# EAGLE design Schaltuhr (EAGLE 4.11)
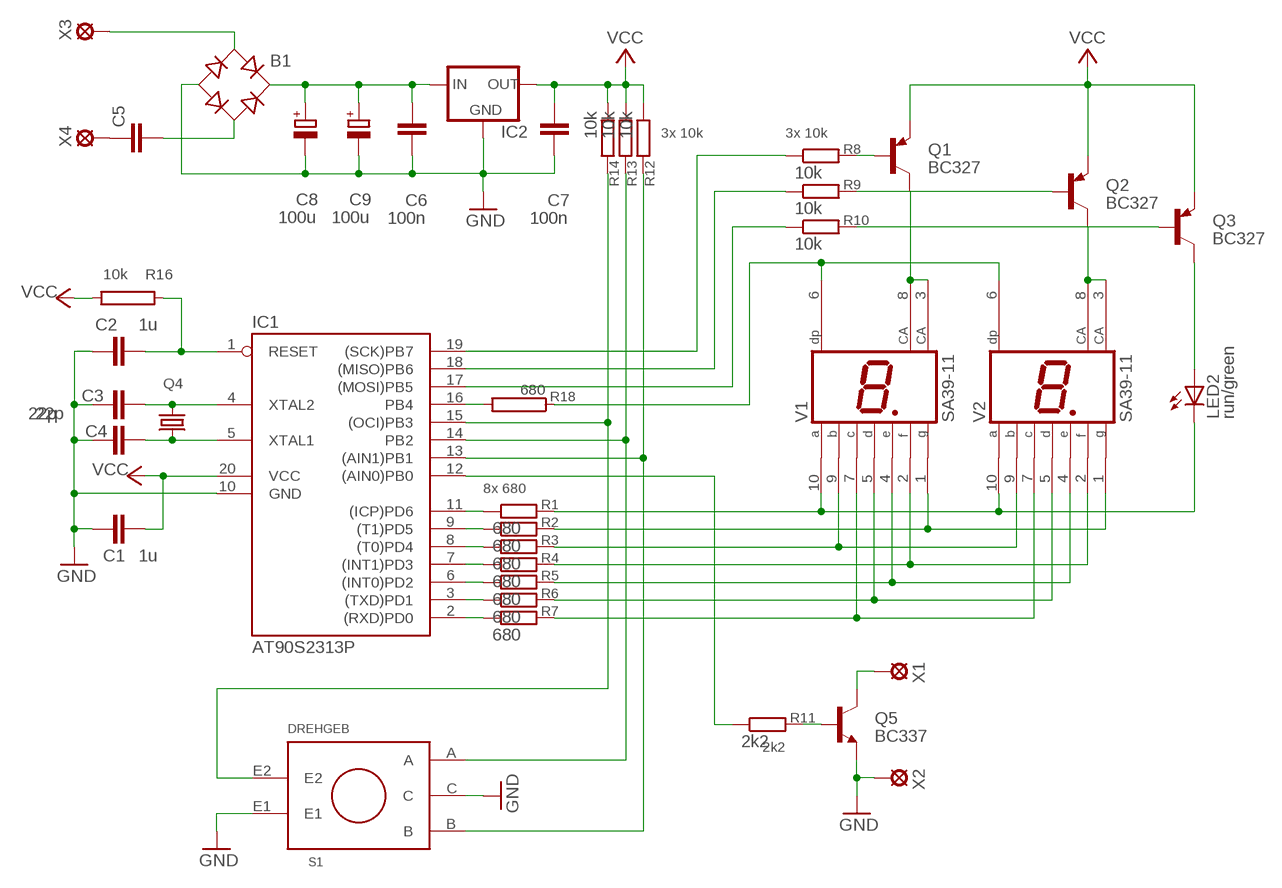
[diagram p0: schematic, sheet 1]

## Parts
B1  B-DIL  [B-DIL]
C1  1u  C-EU050-025X075  [C050-025X075]
C2  1u  C-EU050-025X075  [C050-025X075]
C3  22p  C-EU025-024X044  [C025-024X044]
C4  22p  C-EU025-024X044  [C025-024X044]
C5  C-EU102-043X133  [C102-043X133]
C6  100n  C-EU050-024X044  [C050-024X044]
C7  100n  C-EU050-024X044  [C050-024X044]
C8  100u  CPOL-EUE2.5-7  [E2,5-7]
C9  100u  CPOL-EUE2.5-7  [E2,5-7]
IC1  AT90S2313P  [DIL20]
IC2  78LXX  [78LXX]
LED2  run/green  LED3MM  [LED3MM]
Q1  BC327  [TO92]
Q2  BC327  [TO92]
Q3  BC327  [TO92]
Q4  HC49U-V  [HC49U-V]
Q5  BC337  [TO92]
R1  680  R-EU_R0805  [R0805]
R2  680  R-EU_R0805  [R0805]
R3  680  R-EU_R0805  [R0805]
R4  680  R-EU_R0805  [R0805]
R5  680  R-EU_R0805  [R0805]
R6  680  R-EU_R0805  [R0805]
R7  680  R-EU_R0805  [R0805]
R8  10k  R-EU_0207/10  [0207/10]
R9  10k  R-EU_0207/10  [0207/10]
R10  10k  R-EU_0207/10  [0207/10]
R11  2k2  R-EU_0207/10  [0207/10]
R12  10k  R-EU_0207/10  [0207/10]
R13  10k  R-EU_0207/10  [0207/10]
R14  10k  R-EU_0207/10  [0207/10]
R16  10k  0207/10@2  [1206]
R18  680  0207/10@2  [1206]
S1  DREHGEB  [DREHGEB]
V1  SA39-11  [HDSP-E]
V2  SA39-11  [HDSP-E]
X1  MCS10B  [MCS10B]
X2  MCS10B  [MCS10B]
X3  MCS10B  [MCS10B]
X4  MCS10B  [MCS10B]

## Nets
/RESET: C2.2 IC1.1(RESET) R16.1
A: LED2.K(C) R1.2 V1.10(A) V2.10(A)
B: R3.2 V1.9(B) V2.9(B)
C: R7.2 V1.7(C) V2.7(C)
D: R6.2 V1.5(D) V2.5(D)
E: R5.2 V1.4(E) V2.4(E)
F: R4.2 V1.2(F) V2.2(F)
G: R2.2 V1.1(G) V2.1(G)
GND: B1.- C1.1 C2.1 C3.1 C4.1 C6.1 C7.1 C8.- C9.- IC1.10(GND) IC2.GND Q5.1(E) S1.C S1.E1 X2.MP
N$1: IC1.17((MOSI)PB5) R10.1
N$2: Q2.3(C) V2.3(CA) V2.8(CA)
N$3: Q1.3(C) V1.3(CA) V1.8(CA)
N$4: Q2.2(B) R9.2
N$5: Q3.2(B) R10.2
N$6: Q1.2(B) R8.2
N$7: IC1.11((ICP)PD6) R1.1
N$8: IC1.9((T1)PD5) R2.1
N$9: IC1.8((T0)PD4) R3.1
N$10: IC1.7((INT1)PD3) R4.1
N$11: IC1.6((INT0)PD2) R5.1
N$12: IC1.3((TXD)PD1) R6.1
N$13: IC1.2((RXD)PD0) R7.1
N$14: IC1.12((AIN0)PB0) R11.1
N$15: C3.2 IC1.4(XTAL2) Q4.1
N$16: C4.2 IC1.5(XTAL1) Q4.2
N$17: Q5.3(C) X1.MP
N$18: LED2.A Q3.3(C)
N$19: IC1.18((MISO)PB6) R9.1
N$20: IC1.19((SCK)PB7) R8.1
N$21: B1.AC2 C5.2
N$22: Q5.2(B) R11.2
N$23: IC1.15((OCI)PB3) R14.2 S1.E2
N$24: IC1.14(PB2) R13.2 S1.A
N$25: IC1.13((AIN1)PB1) R12.2 S1.B
N$27: B1.+ C6.2 C8.+ C9.+ IC2.IN
N$28: B1.AC1 X3.MP
N$29: C5.1 X4.MP
N$31: IC1.16(PB4) R18.2
N$32: R18.1 V1.6(DP) V2.6(DP)
VCC: C1.2 C7.2 IC1.20(VCC) IC2.OUT Q1.1(E) Q2.1(E) Q3.1(E) R12.1 R13.1 R14.1 R16.2

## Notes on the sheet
- 3x 10k | 3x 10k
- 8x 680
- 2k2

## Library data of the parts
B1 = rectifier:B-DIL: RECTIFIER
C1-C7 = rcl:C-EU: CAPACITOR, European symbol
C8 C9 = rcl:CPOL-EU: POLARIZED CAPACITOR, European symbol
IC1 = atmel:AT90S2313: MICROCONTROLLER 2 Kbytes FLASH 128 bytes SRAM 128 bytes EEPROM UART
IC2 = v-reg:78LXX: VOLTAGE REGULATOR
LED2 = led:LED: LED
Q1-Q3 = transistor-pnp:BC327: PNP Transistor
Q4 = QUARTZ:HC49U-V
Q5 = transistor-npn:BC337*: NPN Transistor
R1-R14 = rcl:R-EU_: RESISTOR, European symbol
R16 R18 = R:0207/10@2
S1 = SWITCH:DREHGEB
V1 V2 = display-hp:SA39-11
X1-X4 = solpad:MCS10B: SOLDER PAD

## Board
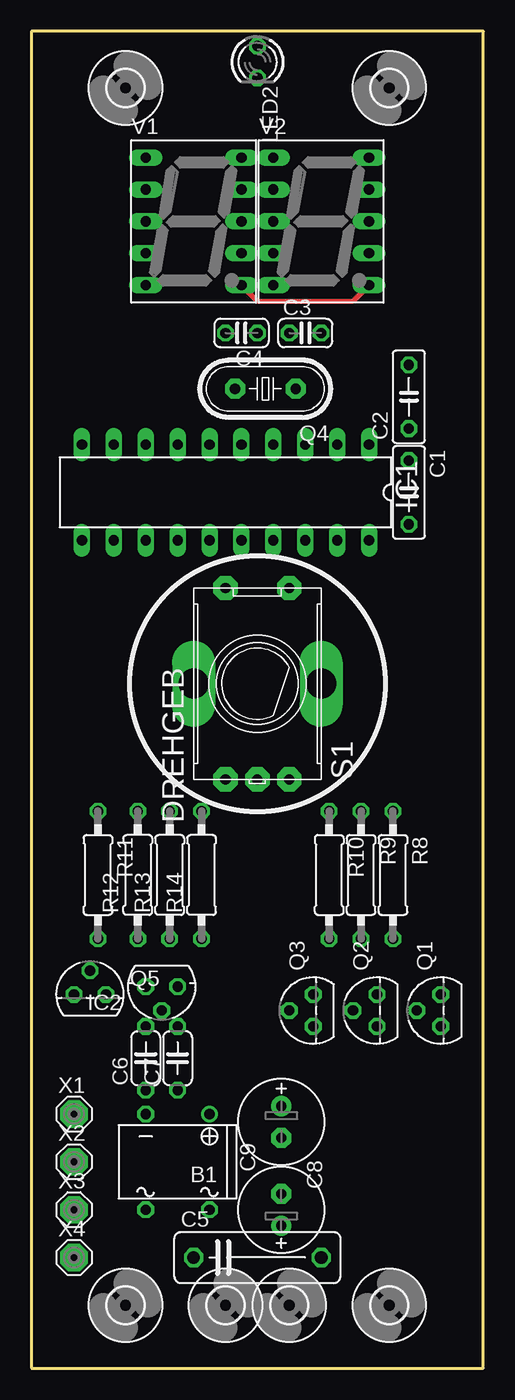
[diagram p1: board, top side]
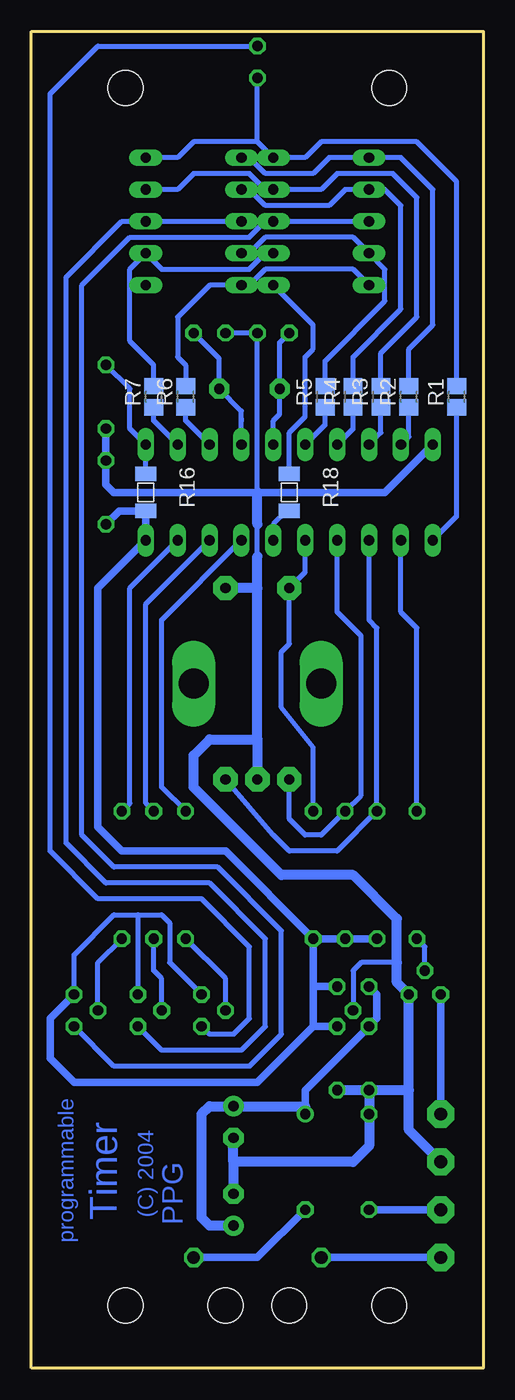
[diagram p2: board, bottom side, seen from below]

Size 36 x 106.5 mm. Coordinates in mm from the lower left corner, seen from the top.
Outline: 36,0 36,106.5 0,106.5 0,0 36,0
Copper layers (1*16): Top 0.035mm / dielectric 1.5mm / Bottom 0.035mm
Design rules "default": minimum track width 10mil, minimum drill 24mil, track to track 8mil, track to pad 8mil, pad to pad 8mil, via to via 8mil, smd to smd 8mil, copper to edge 40mil, drill to drill 8mil, minimum pad ring 10mil, minimum via ring 8mil, stop-mask expansion 4mil, vias tented up to drill 0mil, thermal gap 10mil

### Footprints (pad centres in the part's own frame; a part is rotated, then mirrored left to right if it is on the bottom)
B-DIL = drill 0.813 round: + -2.54,-3.81 | drill 0.813 octagon: - 2.54,-3.81; AC1 2.54,3.81; AC2 -2.54,3.81
C050-025X075 = drill 0.813 octagon: 1 -2.54,0; 2 2.54,0
C025-024X044 = drill 0.813 octagon: 1 -1.27,0; 2 1.27,0
C102-043X133 = drill 1.016 octagon: 1 -5.08,0; 2 5.08,0
C050-024X044 = drill 0.813 octagon: 1 -2.54,0; 2 2.54,0
E2,5-7 = drill 0.813 pad 1.6 round: + -1.27,0 | drill 0.813 pad 1.6 octagon: - 1.27,0
DIL20 = drill 0.813 long: 1 -11.43,-3.81; 2 -8.89,-3.81; 3 -6.35,-3.81; 4 -3.81,-3.81; 5 -1.27,-3.81; 6 1.27,-3.81; 7 3.81,-3.81; 8 6.35,-3.81; 9 8.89,-3.81; 10 11.43,-3.81; 11 11.43,3.81; 12 8.89,3.81; 13 6.35,3.81; 14 3.81,3.81; 15 1.27,3.81; 16 -1.27,3.81; 17 -3.81,3.81; 18 -6.35,3.81; 19 -8.89,3.81; 20 -11.43,3.81
78LXX = drill 0.813 octagon: GND 0,1.905; IN 1.27,0; OUT -1.27,0
LED3MM = drill 0.813 octagon: A -1.27,0; K 1.27,0
TO92 = drill 0.813 octagon: 1 1.27,0; 2 0,1.905; 3 -1.27,0
HC49U-V = drill 0.813 pad 1.6 octagon: 1 -2.413,0; 2 2.413,0
R0805 = smd 1.3 x 1.5: 1 -0.85,0; 2 0.85,0
0207/10 = drill 0.813 octagon: 1 -5.08,0; 2 5.08,0
1206 = smd 1.143 x 1.702: 1 -1.473,0; 2 1.473,0
DREHGEB = drill 0.8 pad 1.93 octagon: A 7.62,-2.54; B 7.62,2.54; C 7.62,0; E1 -7.62,2.54; E2 -7.62,-2.54 | drill 2.4 pad 3 long: M1 0,5.08; M2 0,-5.08
2,8 = hole 2.8: 0,0
HDSP-E = drill 0.813 long: 1 -3.81,5.08; 2 -3.81,2.54; 3 -3.81,0; 4 -3.81,-2.54; 5 -3.81,-5.08; 6 3.81,-5.08; 7 3.81,-2.54; 8 3.81,0; 9 3.81,2.54; 10 3.81,5.08
MCS10B = drill 1.016 pad 2.159 octagon: MP 0,0

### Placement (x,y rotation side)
B1  11.65,16.43 180 top
C1  30.06,69.77 270 top
C2  30.06,77.39 90 top
C3  21.81,82.47 0 top
C4  16.73,82.47 180 top
C5  18,8.81 0 top
C6  9.11,24.68 90 top
C7  11.65,24.68 90 top
C8  19.91,19.61 270 top
C9  19.91,12.62 90 top
IC1  15.46,69.77 180 top
IC2  10.38,30.4 180 top
LED2  18,104.06 270 top
Q1  32.61,28.5 90 top
Q2  27.52,28.5 90 top
Q3  22.45,28.5 90 top
Q4  18.64,78.03 180 top
Q5  4.66,29.77 0 top
R1  2.12,77.39 90 bottom
R2  5.94,77.39 90 bottom
R3  8.16,77.39 90 bottom
R4  10.38,77.39 90 bottom
R5  12.6,77.39 90 bottom
R6  23.71,77.39 90 bottom
R7  26.26,77.39 90 bottom
R8  28.8,39.29 270 top
R9  26.26,39.29 270 top
R10  23.71,39.29 270 top
R11  5.3,39.29 270 top
R12  8.47,39.29 90 top
R13  11.02,39.29 90 top
R14  13.55,39.29 90 top
R16  26.89,69.77 270 bottom
R18  15.46,69.77 270 bottom
S1  18,54.53 270 top
U$1  [2,8]  7.5,5 0 top
U$2  [2,8]  28.5,102 0 top
U$3  [2,8]  7.5,102 0 top
U$4  [2,8]  28.5,5 0 top
U$5  [2,8]  15.46,5 0 top
U$6  [2,8]  20.54,5 0 top
V1  12.92,91.36 0 top
V2  23.08,91.36 0 top
X1  3.39,20.24 0 top
X2  3.39,16.43 0 top
X3  3.39,12.62 0 top
X4  3.39,8.81 0 top

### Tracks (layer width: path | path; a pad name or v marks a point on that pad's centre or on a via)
/RESET  (via drill 0.61)
  Bottom 0.406: C2.2 28.16,78.03 28.16,74.85 IC1.1 R16.1
  other vias: 30.06,79.93 26.89,73.58
A  (via drill 0.61)
  Bottom 0.406: 18,97.71 23.08,97.71 24.35,96.44 V2.10 | R1.2 2.12,94.53 5.3,97.71 12.92,97.71 14.19,96.44 V1.10 18,97.71 | 18,97.71 LED2.K
  other vias: 18,102.79 26.89,96.44 16.73,96.44
B  (via drill 0.61)
  Bottom 0.406: V2.9 24.35,93.9 23.08,95.17 18.64,95.17 17.36,93.9 V1.9 12.92,93.9 11.65,95.17 7.21,95.17 5.3,93.27 5.3,83.74 8.16,80.88 R3.2
  other vias: 26.89,93.9 16.73,93.9
C  (via drill 0.61)
  Bottom 0.406: V1.7 17.36,88.82 18.64,87.55 25.62,87.55 V2.7 28.16,87.55 28.16,81.83 26.26,79.93 R7.2
  other vias: 26.89,88.82 16.73,88.82
D  (via drill 0.61)
  Bottom 0.406: V1.5 10.38,87.55 17.36,87.55 18.64,86.28 V2.5 21.81,86.28 24.35,83.74 24.35,80.56 23.71,79.93 R6.2
  other vias: 19.27,86.28 9.11,86.28
E  (via drill 0.61)
  Bottom 0.406: R5.2 12.6,80.25 7.84,85.01 7.84,87.55 V1.4 10.38,90.09 17.36,90.09 18.64,88.82 V2.4
  other vias: 19.27,88.82 9.11,88.82
F  (via drill 0.61)
  Bottom 0.406: V2.2 18.64,93.9 17.36,92.63 12.29,92.63 11.02,93.9 V1.2 7.84,93.9 6.57,92.63 6.57,84.38 10.38,80.56 R4.2
  other vias: 19.27,93.9 9.11,93.9
G  (via drill 0.61)
  Bottom 0.406: V2.1 18.64,96.44 17.36,95.17 13.55,95.17 12.29,96.44 V1.1 6.57,96.44 4.03,93.9 4.03,83.11 5.94,81.2 R2.2
  other vias: 19.27,96.44 9.11,96.44
GND  (via drill 0.61)
  Bottom 0.406: C3.1 C4.1 18,69.77 | 18,64.69 18,67.23 | 6.89,32.3 9.74,32.3 10.38,31.67 v10.38,28.5
  Bottom 0.61: IC1.10 7.84,69.77 18,69.77 29.43,69.77 30.06,70.41 C1.1 C2.1
  Bottom 0.813: 18,62.15 18,64.69 | 18,67.23 18,69.77 | 18,50.09 S1.C | 18,50.09 21.81,50.09 23.08,48.81 23.08,46.27 16.09,39.29 10.38,39.29 6.89,35.8 6.89,32.3 6.89,30.72 v5.94,29.77 5.94,22.14 | 18,62.15 S1.E1 | 18,50.09 18,62.15 | X2.MP 5.94,18.97 5.94,22.14 | C6.1 C7.1 | C6.1 B1.- 9.11,17.7 10.38,16.43 19.91,16.43 | 19.91,16.43 C9.- | 19.91,16.43 C8.- | 5.94,22.14 C6.1
  other vias: 18,82.47 20.54,82.47 30.06,74.85 30.06,72.31 4.03,73.58 11.65,22.14 9.11,22.14 9.11,20.24 19.91,18.34 19.91,13.89
N$1  (via drill 0.61)
  Bottom 0.406: IC1.17 25.62,59.61 25.62,46.27 R10.1
  other vias: 19.27,65.96 23.71,44.37
N$2  (via drill 0.61)
  Bottom 0.406: V2.3 V2.8 28.8,91.36 33.24,86.92 33.24,41.83 30.06,38.66 21.81,38.66 17.36,34.21 17.36,27.23 19.27,25.32 25.62,25.32 Q2.3
  other vias: 26.89,91.36 19.27,91.36 27.52,27.23
N$3  (via drill 0.61)
  Bottom 0.406: V1.3 V1.8 17.36,91.36 18.64,90.09 28.16,90.09 31.97,86.28 31.97,42.47 29.43,39.92 21.18,39.92 16.09,34.84 16.09,26.59 18.64,24.05 29.43,24.05 Q1.3
  other vias: 16.73,91.36 9.11,91.36 32.61,27.23
N$4  (via drill 0.61)
  Bottom 0.406: Q2.2 25.62,31.04 26.26,31.67 R9.2
  other vias: 26.26,34.21 25.62,28.5
N$5  (via drill 0.61)
  Bottom 0.406: Q3.2 20.54,31.04 R10.2
  other vias: 23.71,34.21 20.54,28.5
N$6  (via drill 0.61)
  Bottom 0.406: Q1.2 30.7,32.3 R8.2
  other vias: 28.8,34.21 30.7,28.5
N$7  (via drill 0.61)
  Bottom 0.406: R1.1 2.12,67.87 IC1.11
  other vias: 4.03,65.96
N$8  (via drill 0.61)
  Bottom 0.406: IC1.9 5.94,74.22 R2.1
  other vias: 6.57,73.58
N$9  (via drill 0.61)
  Bottom 0.406: R3.1 8.16,74.53 IC1.8
  other vias: 9.11,73.58
N$10  (via drill 0.61)
  Bottom 0.406: R4.1 10.38,74.85 IC1.7
  other vias: 11.65,73.58
N$11  (via drill 0.61)
  Bottom 0.406: R5.1 12.6,75.17 IC1.6
  other vias: 14.19,73.58
N$12  (via drill 0.61)
  Bottom 0.406: R6.1 23.71,75.48 IC1.3
  other vias: 21.81,73.58
N$13  (via drill 0.61)
  Bottom 0.406: R7.1 26.26,75.48 IC1.2
  other vias: 24.35,73.58
N$14  (via drill 0.61)
  Bottom 0.406: R11.1 5.3,58.98 6.57,60.24 IC1.12
  other vias: 6.57,65.96 5.3,44.37
N$15  (via drill 0.61)
  Bottom 0.406: IC1.4 19.27,75.48 | 19.27,75.48 19.27,75.61 | C3.2 21.05,80.44 Q4.1 19.27,76.25 19.27,75.48
  other vias: 23.08,82.47 19.27,73.58
N$16  (via drill 0.61)
  Bottom 0.406: C4.2 16.22,81.71 Q4.2 16.22,75.99 16.73,75.48 IC1.5
  other vias: 15.46,82.47 16.73,73.58
N$17  (via drill 0.61)
  Bottom 0.61: X1.MP Q5.3
  other vias: 3.39,29.77
N$18  (via drill 0.61)
  Bottom 0.406: Q3.3 21.81,26.59 19.91,26.59 18.64,27.86 18.64,33.58 22.45,37.38 30.7,37.38 34.51,41.2 34.51,101.52 30.7,105.33 LED2.A
  other vias: 18,105.33 22.45,27.23
N$19  (via drill 0.61)
  Bottom 0.406: IC1.18 26.89,60.88 26.89,45.01 R9.1
  other vias: 21.81,65.96 26.26,44.37
N$20  (via drill 0.61)
  Bottom 0.406: IC1.19 28.16,62.15 28.16,45.01 R8.1
  other vias: 24.35,65.96 28.8,44.37
N$21  (via drill 0.61)
  Bottom 0.61: C5.2 18,8.81 B1.AC2
  other vias: 14.19,12.62 23.08,8.81
N$22  (via drill 0.61)
  Bottom 0.406: Q5.2 4.66,33.58 R11.2
  other vias: 5.3,34.21 4.66,31.67
N$23  (via drill 0.61)
  Bottom 0.406: R14.2 13.55,49.45 16.09,52.62 16.09,57.07 15.46,57.7 S1.E2 14.19,63.42 IC1.15
  other vias: 14.19,65.96 13.55,44.37
N$24  (via drill 0.61)
  Bottom 0.406: S1.A 15.46,43.73 14.19,42.47 12.92,42.47 R13.2 9.74,45.64 9.74,58.34 11.65,60.24 IC1.14
  other vias: 11.65,65.96 11.02,44.37
N$25  (via drill 0.61)
  Bottom 0.406: S1.B 16.73,42.47 15.46,41.2 11.65,41.2 R12.2 8.47,58.98 9.11,59.61 IC1.13
  other vias: 9.11,65.96 8.47,44.37
N$26  (via drill 0.61)
  other vias: 15.46,5
N$27  (via drill 0.61)
  Bottom 0.61: IC2.IN 8.47,29.77 8.47,27.86 v9.11,27.23 14.19,22.14 B1.+
  Bottom 0.813: B1.+ 14.19,20.88 C8.+ 21.81,20.88 22.45,20.24 22.45,11.98 21.81,11.35 C9.+
  other vias: 19.91,20.88 19.91,11.35 14.19,20.24
N$28  (via drill 0.61)
  Bottom 0.61: B1.AC1 X3.MP
  other vias: 9.11,12.62
N$29  (via drill 0.61)
  Bottom 0.61: C5.1 X4.MP
  other vias: 12.92,8.81
N$30  (via drill 0.61)
  other vias: 20.54,5
N$31  (via drill 0.61)
  Bottom 0.406: R18.2 15.66,68.3 16.73,67.23 IC1.16
  other vias: 16.73,65.96
N$32  (via drill 0.61)
  Top 0.406: V1.6 18,85.01 25.62,85.01 V2.6
  Bottom 0.406: V1.6 13.55,83.11 13.55,81.2 14.19,80.56 14.19,75.8 15.46,74.53 R18.1
  other vias: 16.73,86.28
N$33  (via drill 0.61)
  other vias: 7.5,5
N$34  (via drill 0.61)
  other vias: 28.5,5
N$35  (via drill 0.61)
  other vias: 7.5,102
N$36  (via drill 0.61)
  other vias: 28.5,102
N$37  (via drill 0.61 pad 2.18)
  other vias: 12.92,54.53
N$38  (via drill 0.61 pad 2.18)
  other vias: 23.08,54.53
VCC  (via drill 0.61)
  Bottom 0.406: Q3.1 24.98,32.3 24.98,35.48 25.62,36.11 27.52,36.11 | 27.52,36.11 Q2.1 | Q1.1 32.61,32.94 29.43,36.11 27.52,36.11
  Bottom 0.61: Q1.1 34.51,27.86 34.51,24.68 32.61,22.78 18,22.78 13.55,27.23 | R12.1 R13.1 R14.1 | 13.55,27.23 13.55,30.4 | 13.55,30.4 R14.1 | R14.1 20.54,41.2 28.8,41.2 30.7,43.1 30.7,62.15 IC1.20 R16.2 29,68.3 C1.2 | 13.55,30.4 IC2.OUT | v11.65,27.23 13.55,27.23
  other vias: 30.06,67.23 26.89,65.96 8.47,34.21 11.02,34.21 13.55,34.21 22.45,29.77 27.52,29.77 32.61,29.77

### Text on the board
Bottom: programmable | Timer | (C) 2004 | PPG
